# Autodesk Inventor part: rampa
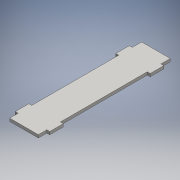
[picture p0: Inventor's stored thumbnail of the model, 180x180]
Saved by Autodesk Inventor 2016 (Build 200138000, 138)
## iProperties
Created: 2016-06
Part Number: rampa
Material: Genérico
Document SubType Name: Modeling
Designer: adm
Density: 1 g/cm^3
Appearance: Valor por defecto
Author: adm
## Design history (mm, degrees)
sketch "Boceto1"
  geometry: L1 (29.5, -125)-(-29.5, -125); L2 (-29.5, 125)-(29.5, 125); L3 (29.5, -125)-(-29.5, 125); L4 (-29.5, -125)-(29.5, 125); L5 (29.5, 117.561)-(35.5, 117.561); L6 (35.5, 117.561)-(35.5, 89.561); L7 (35.5, 89.561)-(29.5, 89.561); L8 (0, 0)-(-55.304, 0); L9 (0, 0)-(0, -42.823); L10 (-29.5, 117.561)-(-35.5, 117.561); L11 (-35.5, 117.561)-(-35.5, 89.561); L12 (-35.5, 89.561)-(-29.5, 89.561); L13 (35.5, -89.56)-(29.5, -89.56); L14 (35.5, -117.56)-(35.5, -89.56); L15 (29.5, -117.56)-(35.5, -117.56); L16 (-35.5, -89.561)-(-29.5, -89.561); L17 (-29.5, -117.561)-(-35.5, -117.561); L18 (-35.5, -117.561)-(-35.5, -89.561); L19 (29.5, -117.56)-(29.5, -125); L20 (-29.5, -125)-(-29.5, -117.561); L21 (-29.5, -89.561)-(-29.5, 89.561); L22 (-29.5, 117.561)-(-29.5, 125); L23 (29.5, 125)-(29.5, 117.561); L24 (29.5, 89.561)-(29.5, -89.56)
  constraints: 48 end point, 12 symmetric about line, 11 parallel, 4 perpendicular, 3 horizontal, 2 midpoint, 1 vertical
  dimensions: "d0" = 59 distance of L1.start L1.end; "d1" = 250 distance of L2.end L1.start; "d2" = 28 distance of L5.end L6.end; "d3" = 6 distance of L6.end L7.end; "d4" = 117.5605 distance from line of L5 L8.start
extrude "Extrusión1" new body sketch "Boceto1" distance "d5" = 6; taper "d6" = 0 deg
sketch "Boceto2"
  geometry: L1 (29.5, 125)-(-29.5, 125) reference; L2 (-29.5, 125)-(29.5, 125); L3 (29.5, 125)-(29.5, 137); L4 (29.5, 137)-(-29.5, 137); L5 (-29.5, 137)-(-29.5, 125); 1 further point
  constraints: 8 end point, 2 parallel, 1 horizontal, 1 perpendicular
  dimensions: "d7" = 12 distance of L3.end L2.end
extrude "Extrusión2" join sketch "Boceto2" distance "d8" = 6; taper "d9" = 0 deg
sketch "Boceto3"
  geometry: L1 (-29.5, -125)-(29.5, -125) reference; L2 (-29.5, -125)-(29.5, -125); L3 (29.5, -125)-(29.5, -135); L4 (29.5, -135)-(-29.5, -135); L5 (-29.5, -135)-(-29.5, -125); 1 further point
  constraints: 8 end point, 2 parallel, 1 horizontal, 1 perpendicular
  dimensions: "d10" = 10 distance of L2.end L3.end
extrude "Extrusión3" join sketch "Boceto3" distance "d11" = 6; taper "d12" = 0 deg
node "Sólido1"
